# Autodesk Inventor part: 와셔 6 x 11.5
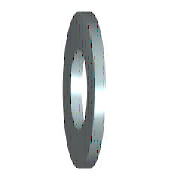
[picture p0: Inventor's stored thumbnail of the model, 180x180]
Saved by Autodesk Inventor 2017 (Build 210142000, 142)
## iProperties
IsCustomPart: 1
Created: 2012-02
Part Number: 와셔 6 x 11.5
Material: 강철, 연강
Description: 평면 와셔
Document SubType Name: Modeling
Standard: KS B 1326
Designer: mduedu
Standards Organization: KS
Language: ko-KR
Size Designation: 6x11.5
Categories: <MemberInstance><Categories><Category DisplayName="조임쇠" InternalName="e4da775c-781d-43d5-af7c-5136215cf5a6" Mnemonic="FSTN"><Category DisplayName="와셔" InternalN
Density: 7.86 g/cm^3
Mass: 0.901687 g
Surface Area: 2.33373 cm^2
Volume: 0.114718 cm^3
Appearance: 주황색
Author: mduedu
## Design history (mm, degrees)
sketch "스케치"
  geometry: C1 r 5.75 at (0, 0); C2 r 3.2 at (0, 0); 1 further point
  constraints: 2 centre point, 2 coincident
  dimensions: "d0" = 6.4 diameter of C2 (= SD1); "d1" = 11.5 diameter of C1 (= SD2)
extrude "본체" new body sketch "스케치" distance "d2" = 1.6 (= SD); taper "d3" = 0 deg
workaxis "Work Axis1"
workplane "Work Plane1"
body "Solid1"
other parameters: "SD1" = 6.4 [user parameter; used in 1 equation term], "SD2" = 11.5 [user parameter; used in 1 equation term], "SD" = 1.6 [user parameter; used in 1 equation term], "d4" = 0, "d5" = 0, "d6" = 0, "d7" = 0, "NND" = 6 [user parameter]
